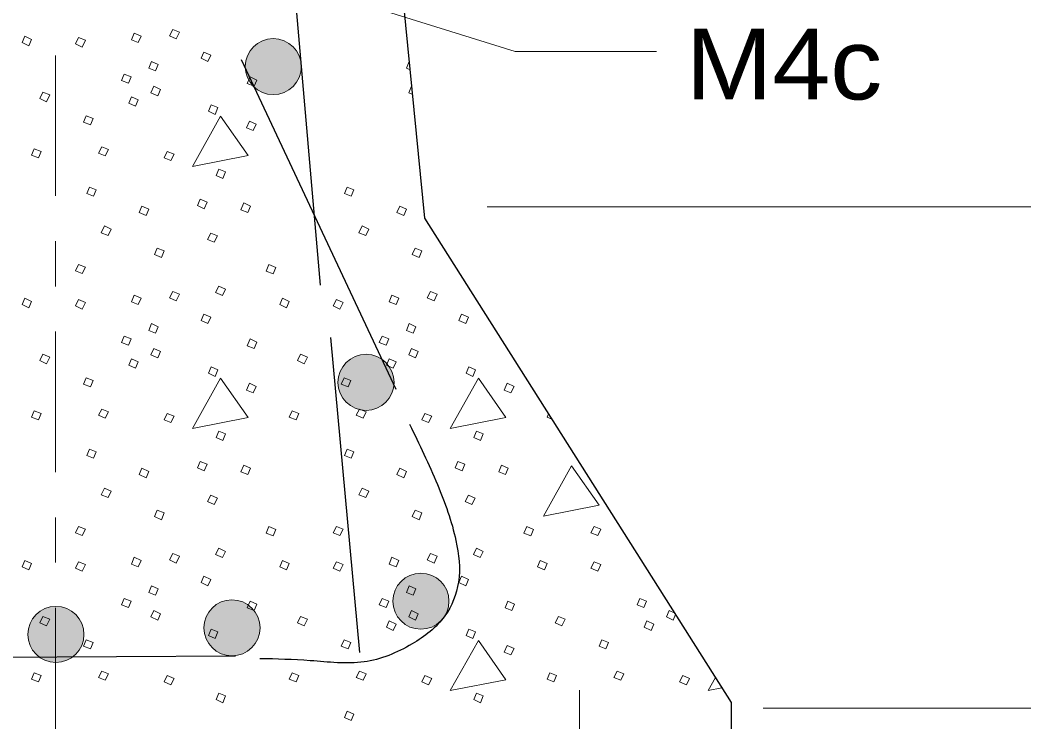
# Model space of a CAD drawing. Extents: x 1083.1 to 1123, y 697.4 to 741.4.
# Drawn here: x 1090.714 to 1092.929, y 713.855 to 715.405 of the extents above; entities that cross this region are included whole.
import ezdxf

# ---------------------------------------------------------------- set-up
doc = ezdxf.new("R2010")
doc.units = 0
doc.header["$LTSCALE"] = 0.062
doc.linetypes.add('DOT_DASHED', pattern=[7.7, 5, -1.2, 0.3, -1.2])
doc.layers.add('1', color=7, linetype='Continuous', lineweight=13)

msp = doc.modelspace()

# ---------------------------------------------------------------- hatches: boundary and pattern name
at = {"layer": '1'}
h = msp.add_hatch(color=256, dxfattribs=at)
edge = h.paths.add_edge_path()
edge.add_ellipse((1091.27248, 715.30209), major_axis=(0.06191, 0), ratio=0.9998948, start_angle=0, end_angle=360)
h = msp.add_hatch(color=256, dxfattribs=at)
edge = h.paths.add_edge_path()
edge.add_ellipse((1091.47713, 714.60502), major_axis=(0.06191, 0), ratio=0.9998948, start_angle=0, end_angle=360)
h = msp.add_hatch(color=256, dxfattribs=at)
edge = h.paths.add_edge_path()
edge.add_ellipse((1091.59816, 714.12194), major_axis=(0.06191, 0), ratio=0.9998948, start_angle=0, end_angle=360)
h = msp.add_hatch(color=256, dxfattribs=at)
edge = h.paths.add_edge_path()
edge.add_ellipse((1091.18128, 714.06308), major_axis=(0.06191, 0), ratio=0.9998948, start_angle=0, end_angle=360)
h = msp.add_hatch(color=256, dxfattribs=at)
edge = h.paths.add_edge_path()
edge.add_ellipse((1090.79275, 714.04852), major_axis=(0.06191, 0), ratio=0.9998948, start_angle=0, end_angle=360)

# ---------------------------------------------------------------- linework, layer by layer
at = {"layer": '1', "linetype": 'DOT_DASHED'}
msp.add_line((1090.7915, 717.157), (1090.7915, 713.82992), dxfattribs=at)
at = {"layer": '1', "lineweight": 25}
for p, q in [((1091.37642, 714.81975), (1091.30158, 715.68408)), ((1091.20158, 715.318), (1091.54275, 714.58992)), ((1091.46342, 714.00842), (1091.39967, 714.70375)), ((1090.36958, 713.99625), (1091.18933, 714.00117))]:
    msp.add_line(p, q, dxfattribs=at)
at = {"layer": '1'}
for p, q in [((1091.57225, 715.31342), (1091.5725, 715.31333)), ((1091.57725, 715.25858), (1091.57783, 715.25825)), ((1091.74475, 714.99225), (1093.95242, 714.99225)), ((1092.146, 714.10125), (1092.15825, 714.09558)), ((1091.94833, 713.92525), (1091.94833, 713.57625)), ((1092.35375, 713.88608), (1093.95242, 713.88608))]:
    msp.add_line(p, q, dxfattribs=at)
at = {"layer": '1', "lineweight": 25}
msp.add_lwpolyline([(1092.86625, 713.35117), (1092.28325, 713.35117), (1092.28325, 713.89792), (1091.6065, 714.96742), (1091.41967, 716.86658)], dxfattribs=at)
at = {"layer": '1'}
for points in [[(1091.14858, 715.54108), (1091.8065, 715.33567), (1092.11775, 715.33567)], [(1091.57425, 715.29525), (1091.56625, 715.29842), (1091.57225, 715.31342)], [(1091.57967, 715.24067), (1091.57125, 715.24458), (1091.57725, 715.25858)], [(1091.785, 714.68533), (1091.78383, 714.68592), (1091.78408, 714.68667)], [(1091.88708, 714.52408), (1091.87658, 714.52825), (1091.87975, 714.53567)], [(1092.16017, 714.0925), (1092.155, 714.08025), (1092.14, 714.08725), (1092.146, 714.10125)], [(1092.248, 713.95367), (1092.23183, 713.92467), (1092.2625, 713.93067)]]:
    msp.add_lwpolyline(points, dxfattribs=at)
for points in [[(1091.05042, 715.38425), (1091.06542, 715.37825), (1091.05842, 715.36333), (1091.04342, 715.37025)], [(1090.72417, 715.36925), (1090.73908, 715.36233), (1090.73317, 715.34833), (1090.71817, 715.35533)], [(1090.84292, 715.36625), (1090.85783, 715.36033), (1090.85083, 715.34533), (1090.83592, 715.35233)], [(1090.96558, 715.37625), (1090.98058, 715.36925), (1090.97458, 715.35533), (1090.95967, 715.36133)], [(1091.11925, 715.33433), (1091.13425, 715.32742), (1091.12825, 715.31342), (1091.11325, 715.32042)], [(1091.0035, 715.31342), (1091.0185, 715.30642), (1091.0125, 715.2925), (1090.99758, 715.29842)], [(1090.94367, 715.2855), (1090.95867, 715.2795), (1090.95267, 715.2655), (1090.93767, 715.2715)], [(1091.22108, 715.2795), (1091.236, 715.2725), (1091.23, 715.25858), (1091.21508, 715.2645)], [(1091.0085, 715.25858), (1091.0235, 715.25158), (1091.0175, 715.23758), (1091.0025, 715.24458)], [(1090.76408, 715.24558), (1090.779, 715.23958), (1090.77208, 715.22467), (1090.75708, 715.23158)], [(1090.95967, 715.23558), (1090.97458, 715.22858), (1090.96858, 715.21467), (1090.95367, 715.22167)], [(1091.13525, 715.21767), (1091.15017, 715.21167), (1091.14425, 715.19667), (1091.12925, 715.20367)], [(1090.85983, 715.19367), (1090.87483, 715.18767), (1090.86883, 715.17375), (1090.85383, 715.17975)], [(1091.15617, 715.19267), (1091.09433, 715.08192), (1091.21708, 715.10592)], [(1091.22008, 715.18175), (1091.235, 715.17475), (1091.228, 715.16075), (1091.21308, 715.16675)], [(1090.74508, 715.12083), (1090.76008, 715.11492), (1090.75408, 715.10092), (1090.73908, 715.10692)], [(1090.89375, 715.12483), (1090.90875, 715.11883), (1090.90175, 715.10492), (1090.88683, 715.11092)], [(1091.03842, 715.11492), (1091.05342, 715.10892), (1091.04642, 715.09492), (1091.0315, 715.10092)], [(1091.15217, 715.076), (1091.16717, 715.07), (1091.16117, 715.055), (1091.14625, 715.062)], [(1090.86683, 715.03608), (1090.88183, 715.03008), (1090.87583, 715.01608), (1090.86083, 715.02208)], [(1091.43558, 715.03608), (1091.4505, 715.03008), (1091.44458, 715.01608), (1091.42958, 715.02208)], [(1091.11133, 715.00917), (1091.12625, 715.00317), (1091.12025, 714.98817), (1091.10533, 714.99517)], [(1090.98258, 714.99417), (1090.99758, 714.98717), (1090.99158, 714.97325), (1090.97658, 714.98017)], [(1091.20708, 715.00117), (1091.22208, 714.99417), (1091.21608, 714.98017), (1091.20108, 714.98617)], [(1091.55133, 714.99417), (1091.56625, 714.98717), (1091.56033, 714.97325), (1091.54533, 714.98017)], [(1090.89975, 714.95025), (1090.91475, 714.94325), (1090.90775, 714.92933), (1090.89275, 714.93533)], [(1091.4685, 714.95025), (1091.4835, 714.94325), (1091.4765, 714.92933), (1091.4615, 714.93533)], [(1091.13425, 714.93433), (1091.14917, 714.92833), (1091.14225, 714.91433), (1091.12725, 714.92033)], [(1091.0165, 714.90142), (1091.0315, 714.89542), (1091.0255, 714.88042), (1091.0105, 714.88742)], [(1091.58525, 714.90142), (1091.60017, 714.89542), (1091.59425, 714.88042), (1091.57925, 714.88742)], [(1090.84292, 714.8655), (1090.85783, 714.8595), (1090.85083, 714.8455), (1090.83592, 714.8515)], [(1091.26292, 714.8655), (1091.27792, 714.8585), (1091.27192, 714.8445), (1091.257, 714.8505)], [(1091.15217, 714.81758), (1091.16717, 714.81058), (1091.16017, 714.79658), (1091.14525, 714.80358)], [(1090.72417, 714.79067), (1090.73908, 714.78367), (1090.73317, 714.76967), (1090.71817, 714.77667)], [(1090.84292, 714.78767), (1090.85783, 714.78167), (1090.85083, 714.76667), (1090.83592, 714.77367)], [(1090.96558, 714.79758), (1090.98058, 714.79067), (1090.97458, 714.77667), (1090.95967, 714.78267)], [(1091.05042, 714.80558), (1091.06542, 714.79958), (1091.05842, 714.78467), (1091.04342, 714.79167)], [(1091.29292, 714.79067), (1091.30783, 714.78367), (1091.30183, 714.76967), (1091.28692, 714.77667)], [(1091.41158, 714.78767), (1091.42658, 714.78167), (1091.41958, 714.76667), (1091.40467, 714.77367)], [(1091.53433, 714.79758), (1091.54933, 714.79067), (1091.54333, 714.77667), (1091.52833, 714.78267)], [(1091.61917, 714.80558), (1091.63408, 714.79958), (1091.62717, 714.78467), (1091.61217, 714.79167)], [(1091.11925, 714.75575), (1091.13425, 714.74875), (1091.12825, 714.73475), (1091.11325, 714.74175)], [(1091.688, 714.75575), (1091.703, 714.74875), (1091.697, 714.73475), (1091.682, 714.74175)], [(1091.0035, 714.73475), (1091.0185, 714.72775), (1091.0125, 714.71383), (1090.99758, 714.71983)], [(1091.57225, 714.73475), (1091.58725, 714.72775), (1091.58125, 714.71383), (1091.56625, 714.71983)], [(1090.94367, 714.70683), (1090.95867, 714.70083), (1090.95267, 714.68692), (1090.93767, 714.69283)], [(1091.22108, 714.70083), (1091.236, 714.69383), (1091.23, 714.67992), (1091.21508, 714.68592)], [(1091.51242, 714.70683), (1091.52733, 714.70083), (1091.52142, 714.68692), (1091.50642, 714.69283)], [(1091.0085, 714.67992), (1091.0235, 714.67292), (1091.0175, 714.65892), (1091.0025, 714.66592)], [(1091.57725, 714.67992), (1091.59225, 714.67292), (1091.58625, 714.65892), (1091.57125, 714.66592)], [(1090.76408, 714.66692), (1090.779, 714.66092), (1090.77208, 714.646), (1090.75708, 714.65292)], [(1090.95967, 714.65692), (1090.97458, 714.65), (1090.96858, 714.636), (1090.95367, 714.643)], [(1091.33283, 714.66692), (1091.34775, 714.66092), (1091.34075, 714.646), (1091.32583, 714.65292)], [(1091.52833, 714.65692), (1091.54333, 714.65), (1091.53733, 714.636), (1091.52242, 714.643)], [(1091.13525, 714.639), (1091.15017, 714.633), (1091.14425, 714.61808), (1091.12925, 714.625)], [(1091.704, 714.639), (1091.71892, 714.633), (1091.71292, 714.61808), (1091.698, 714.625)], [(1090.85983, 714.61508), (1090.87483, 714.60908), (1090.86883, 714.59508), (1090.85383, 714.60108)], [(1091.15617, 714.61408), (1091.09433, 714.50333), (1091.21708, 714.52725)], [(1091.42858, 714.61508), (1091.44358, 714.60908), (1091.43758, 714.59508), (1091.42258, 714.60108)], [(1091.72492, 714.61408), (1091.66308, 714.50333), (1091.78583, 714.52725)], [(1091.22008, 714.60308), (1091.235, 714.59608), (1091.228, 714.58208), (1091.21308, 714.58808)], [(1091.78875, 714.60308), (1091.80375, 714.59608), (1091.79675, 714.58208), (1091.78183, 714.58808)], [(1090.74508, 714.54225), (1090.76008, 714.53625), (1090.75408, 714.52225), (1090.73908, 714.52825)], [(1090.89375, 714.54617), (1090.90875, 714.54025), (1090.90175, 714.52625), (1090.88683, 714.53225)], [(1091.31383, 714.54225), (1091.32883, 714.53625), (1091.32283, 714.52225), (1091.30783, 714.52825)], [(1091.4625, 714.54617), (1091.4775, 714.54025), (1091.4705, 714.52625), (1091.4555, 714.53225)], [(1091.03842, 714.53625), (1091.05342, 714.53025), (1091.04642, 714.51625), (1091.0315, 714.52225)], [(1091.60717, 714.53625), (1091.62217, 714.53025), (1091.61517, 714.51625), (1091.60017, 714.52225)], [(1091.15217, 714.49733), (1091.16717, 714.49133), (1091.16117, 714.47633), (1091.14625, 714.48333)], [(1091.72092, 714.49733), (1091.73592, 714.49133), (1091.72992, 714.47633), (1091.71492, 714.48333)], [(1090.86683, 714.45742), (1090.88183, 714.45142), (1090.87583, 714.43742), (1090.86083, 714.44342)], [(1091.43558, 714.45742), (1091.4505, 714.45142), (1091.44458, 714.43742), (1091.42958, 714.44342)], [(1091.11133, 714.4305), (1091.12625, 714.4245), (1091.12025, 714.4095), (1091.10533, 714.4165)], [(1091.68, 714.4305), (1091.695, 714.4245), (1091.689, 714.4095), (1091.674, 714.4165)], [(1090.98258, 714.4155), (1090.99758, 714.4085), (1090.99158, 714.39458), (1090.97658, 714.4015)], [(1091.20708, 714.4225), (1091.22208, 714.4155), (1091.21608, 714.4015), (1091.20108, 714.4075)], [(1091.55133, 714.4155), (1091.56625, 714.4085), (1091.56033, 714.39458), (1091.54533, 714.4015)], [(1091.77583, 714.4225), (1091.79075, 714.4155), (1091.78475, 714.4015), (1091.76983, 714.4075)], [(1091.9305, 714.4205), (1091.86858, 714.30975), (1091.99133, 714.33367)], [(1090.89975, 714.37158), (1090.91475, 714.36467), (1090.90775, 714.35067), (1090.89275, 714.35667)], [(1091.4685, 714.37158), (1091.4835, 714.36467), (1091.4765, 714.35067), (1091.4615, 714.35667)], [(1091.13425, 714.35567), (1091.14917, 714.34967), (1091.14225, 714.33567), (1091.12725, 714.34167)], [(1091.703, 714.35567), (1091.71792, 714.34967), (1091.71092, 714.33567), (1091.696, 714.34167)], [(1091.0165, 714.32275), (1091.0315, 714.31675), (1091.0255, 714.30175), (1091.0105, 714.30875)], [(1091.58525, 714.32275), (1091.60017, 714.31675), (1091.59425, 714.30175), (1091.57925, 714.30875)], [(1090.84292, 714.28683), (1090.85783, 714.28083), (1090.85083, 714.26683), (1090.83592, 714.27283)], [(1091.26292, 714.28683), (1091.27792, 714.27983), (1091.27192, 714.26583), (1091.257, 714.27183)], [(1091.41158, 714.28683), (1091.42658, 714.28083), (1091.41958, 714.26683), (1091.40467, 714.27283)], [(1091.83167, 714.28683), (1091.84667, 714.27983), (1091.84067, 714.26583), (1091.82567, 714.27183)], [(1091.98033, 714.28683), (1091.99533, 714.28083), (1091.98833, 714.26683), (1091.97333, 714.27283)], [(1091.15217, 714.23892), (1091.16717, 714.23192), (1091.16017, 714.218), (1091.14525, 714.22492)], [(1091.72092, 714.23892), (1091.73592, 714.23192), (1091.72892, 714.218), (1091.71392, 714.22492)], [(1090.72417, 714.212), (1090.73908, 714.205), (1090.73317, 714.191), (1090.71817, 714.198)], [(1090.84292, 714.209), (1090.85783, 714.203), (1090.85083, 714.18808), (1090.83592, 714.195)], [(1090.96558, 714.219), (1090.98058, 714.212), (1090.97458, 714.198), (1090.95967, 714.204)], [(1091.05042, 714.22692), (1091.06542, 714.221), (1091.05842, 714.206), (1091.04342, 714.213)], [(1091.29292, 714.212), (1091.30783, 714.205), (1091.30183, 714.191), (1091.28692, 714.198)], [(1091.41158, 714.209), (1091.42658, 714.203), (1091.41958, 714.18808), (1091.40467, 714.195)], [(1091.53433, 714.219), (1091.54933, 714.212), (1091.54333, 714.198), (1091.52833, 714.204)], [(1091.61917, 714.22692), (1091.63408, 714.221), (1091.62717, 714.206), (1091.61217, 714.213)], [(1091.86158, 714.212), (1091.87658, 714.205), (1091.87058, 714.191), (1091.85567, 714.198)], [(1091.98033, 714.209), (1091.99533, 714.203), (1091.98833, 714.18808), (1091.97333, 714.195)], [(1091.11925, 714.17708), (1091.13425, 714.17008), (1091.12825, 714.15608), (1091.11325, 714.16308)], [(1091.688, 714.17708), (1091.703, 714.17008), (1091.697, 714.15608), (1091.682, 714.16308)], [(1091.0035, 714.15608), (1091.0185, 714.14917), (1091.0125, 714.13517), (1090.99758, 714.14117)], [(1091.57225, 714.15608), (1091.58725, 714.14917), (1091.58125, 714.13517), (1091.56625, 714.14117)], [(1090.94367, 714.12817), (1090.95867, 714.12217), (1090.95267, 714.10825), (1090.93767, 714.11417)], [(1091.22108, 714.12217), (1091.236, 714.11517), (1091.23, 714.10125), (1091.21508, 714.10725)], [(1091.51242, 714.12817), (1091.52733, 714.12217), (1091.52142, 714.10825), (1091.50642, 714.11417)], [(1091.78975, 714.12217), (1091.80475, 714.11517), (1091.79875, 714.10125), (1091.78383, 714.10725)], [(1092.08117, 714.12817), (1092.09608, 714.12217), (1092.09008, 714.10825), (1092.07517, 714.11417)], [(1091.0085, 714.10125), (1091.0235, 714.09425), (1091.0175, 714.08025), (1091.0025, 714.08725)], [(1091.57725, 714.10125), (1091.59225, 714.09425), (1091.58625, 714.08025), (1091.57125, 714.08725)], [(1090.76408, 714.08825), (1090.779, 714.08225), (1090.77208, 714.06733), (1090.75708, 714.07433)], [(1091.33283, 714.08825), (1091.34775, 714.08225), (1091.34075, 714.06733), (1091.32583, 714.07433)], [(1091.52833, 714.07833), (1091.54333, 714.07133), (1091.53733, 714.05733), (1091.52242, 714.06433)], [(1091.9015, 714.08825), (1091.9165, 714.08225), (1091.9095, 714.06733), (1091.89458, 714.07433)], [(1092.09708, 714.07833), (1092.11208, 714.07133), (1092.10608, 714.05733), (1092.09108, 714.06433)], [(1091.13525, 714.06033), (1091.15017, 714.05433), (1091.14425, 714.03942), (1091.12925, 714.04633)], [(1091.704, 714.06033), (1091.71892, 714.05433), (1091.71292, 714.03942), (1091.698, 714.04633)], [(1090.85983, 714.03642), (1090.87483, 714.03042), (1090.86883, 714.01642), (1090.85383, 714.02242)], [(1091.42858, 714.03642), (1091.44358, 714.03042), (1091.43758, 714.01642), (1091.42258, 714.02242)], [(1091.72492, 714.03542), (1091.66308, 713.92467), (1091.78583, 713.94858)], [(1091.99733, 714.03642), (1092.01225, 714.03042), (1092.00633, 714.01642), (1091.99133, 714.02242)], [(1091.78875, 714.02442), (1091.80375, 714.01742), (1091.79675, 714.0035), (1091.78183, 714.00942)], [(1090.89375, 713.96758), (1090.90875, 713.96158), (1090.90175, 713.94758), (1090.88683, 713.95358)], [(1091.4625, 713.96758), (1091.4775, 713.96158), (1091.4705, 713.94758), (1091.4555, 713.95358)], [(1092.03125, 713.96758), (1092.04625, 713.96158), (1092.03925, 713.94758), (1092.02425, 713.95358)], [(1090.74508, 713.96358), (1090.76008, 713.95758), (1090.75408, 713.94358), (1090.73908, 713.94958)], [(1091.03842, 713.95758), (1091.05342, 713.95158), (1091.04642, 713.93758), (1091.0315, 713.94358)], [(1091.31383, 713.96358), (1091.32883, 713.95758), (1091.32283, 713.94358), (1091.30783, 713.94958)], [(1091.60717, 713.95758), (1091.62217, 713.95158), (1091.61517, 713.93758), (1091.60017, 713.94358)], [(1091.88258, 713.96358), (1091.8975, 713.95758), (1091.89158, 713.94358), (1091.87658, 713.94958)], [(1092.17592, 713.95758), (1092.19092, 713.95158), (1092.18392, 713.93758), (1092.16892, 713.94358)], [(1091.15217, 713.91867), (1091.16717, 713.91267), (1091.16117, 713.89775), (1091.14625, 713.90467)], [(1091.72092, 713.91867), (1091.73592, 713.91267), (1091.72992, 713.89775), (1091.71492, 713.90467)], [(1091.43558, 713.87875), (1091.4505, 713.87275), (1091.44458, 713.85883), (1091.42958, 713.86483)]]:
    msp.add_lwpolyline(points, close=True, dxfattribs=at)
for centre in [(1091.27248, 715.30209), (1091.47713, 714.60502), (1091.59816, 714.12194), (1091.18128, 714.06308), (1090.79275, 714.04852)]:
    msp.add_ellipse(centre, major_axis=(0.06191, 0), ratio=0.999895, dxfattribs=at)
at = {"layer": '1', "lineweight": 25}
msp.add_spline([(1091.57333, 714.5125), (1091.6345, 714.3795), (1091.6755, 714.25567), (1091.68108, 714.16408), (1091.65108, 714.08933), (1091.57858, 714.0275), (1091.47275, 713.98783), (1091.35417, 713.99058), (1091.2425, 713.99492)], degree=3, dxfattribs=at)

# ---------------------------------------------------------------- texts
at = {"layer": '1', "width": 1.1}
msp.add_text('M4c', height=0.156, dxfattribs=at).set_placement((1092.18267, 715.22958))

doc.saveas('drawing.dxf')
